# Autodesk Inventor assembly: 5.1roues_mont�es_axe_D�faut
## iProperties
Created: 2011-01
Part Number: 5.1roues_mont�es_axe_D�faut
Document SubType Name: Assembly
Designer: eric
Mass: 610.809 g
Surface Area: 3296.9 cm^2
Volume: 610.809 cm^3
Density: 1 g/cm^3
Author: eric
